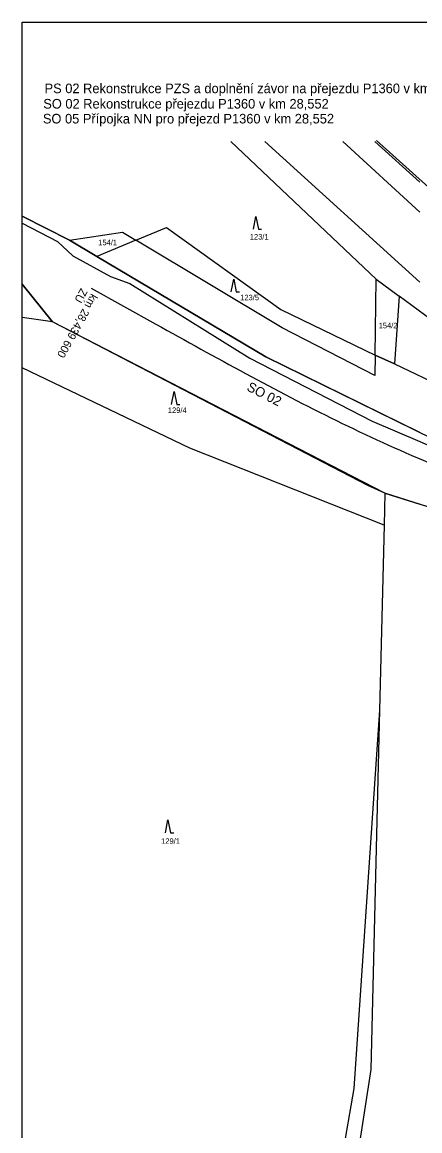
# Model space of a CAD drawing. Extents: x -792659 to -786947, y -1118170 to -1109641.
# Drawn here: x -789729.4 to -789667.2, y -1114376.9 to -1114203.8 of the extents above; entities that cross this region are included whole.
import ezdxf

# ---------------------------------------------------------------- set-up
doc = ezdxf.new("R2010")
doc.units = 0
doc.layers.add('1', color=7, linetype='Continuous')

# ---------------------------------------------------------------- blocks, each defined once
blk = doc.blocks.new('Z30801')
at = {"layer": '1'}
for p, q in [((-0.8, 0), (0, 4)), ((0, 4), (0.8, 0)), ((0.8, 0), (1.8, 0))]:
    blk.add_line(p, q, dxfattribs=at)

msp = doc.modelspace()

# ---------------------------------------------------------------- linework, layer by layer
at = {"layer": '1'}
for p, q in [((-789674.05, -1114243.92), (-789696.77, -1114222.42)), ((-789667.24, -1114244.36), (-789691.43, -1114222.42)), ((-789679.26, -1114222.42), (-789667.24, -1114233.46)), ((-789667.24, -1114228.73), (-789674.25, -1114222.42)), ((-789721.98, -1114237.82), (-789729.37, -1114234.09)), ((-789711.61, -1114237.83), (-789706.83, -1114235.81)), ((-789706.83, -1114235.81), (-789688.94, -1114248.62)), ((-789721.98, -1114237.82), (-789713.71, -1114236.57)), ((-789717.72, -1114240.35), (-789721.98, -1114237.82)), ((-789711.61, -1114237.83), (-789717.72, -1114240.35)), ((-789713.71, -1114236.57), (-789711.61, -1114237.83)), ((-789688.76, -1114251.49), (-789711.61, -1114237.83)), ((-789691.28, -1114256.01), (-789717.72, -1114240.35)), ((-789729.37, -1114244.66), (-789724.61, -1114250.58)), ((-789674.22, -1114255.79), (-789674.05, -1114243.92)), ((-789674.05, -1114243.92), (-789670.47, -1114246.55)), ((-789718.58, -1114245.32), (-789708.47, -1114250.93)), ((-789718.58, -1114245.32), (-789708.47, -1114250.93)), ((-789718.58, -1114245.32), (-789708.47, -1114250.93)), ((-789718.58, -1114245.32), (-789708.47, -1114250.93)), ((-789670.47, -1114246.55), (-789671.17, -1114257.11)), ((-789665.52, -1114250.19), (-789670.47, -1114246.55)), ((-789724.61, -1114250.58), (-789729.37, -1114249.9)), ((-789688.94, -1114248.62), (-789674.22, -1114255.79)), ((-789675.34, -1114276.11), (-789724.61, -1114250.58)), ((-789674.27, -1114258.96), (-789688.76, -1114251.49)), ((-789667.24, -1114267.85), (-789691.28, -1114256.01)), ((-789674.22, -1114255.79), (-789674.27, -1114258.96)), ((-789674.22, -1114255.79), (-789671.17, -1114257.11)), ((-789671.17, -1114257.11), (-789674.22, -1114255.79)), ((-789703.15, -1114270.28), (-789729.37, -1114257.73)), ((-789671.17, -1114257.11), (-789662.15, -1114261.44)), ((-789672.8, -1114282.32), (-789703.15, -1114270.28)), ((-789672.68, -1114277.31), (-789675.34, -1114276.11)), ((-789672.68, -1114277.31), (-789672.8, -1114282.32)), ((-789672.68, -1114277.31), (-789667.24, -1114279.04)), ((-789672.8, -1114282.32), (-789673.52, -1114311.19)), ((-789673.52, -1114311.19), (-789677.54, -1114370.31)), ((-789673.52, -1114311.19), (-789674.91, -1114367.33)), ((-789674.91, -1114367.33), (-789681.24, -1114408.94)), ((-789677.54, -1114370.31), (-789686.2, -1114419.31))]:
    msp.add_line(p, q, dxfattribs=at)
msp.add_lwpolyline([(-789729.37, -1114203.77), (-789353, -1114203.77), (-789353, -1114466.81), (-789729.37, -1114466.81)], close=True, dxfattribs=at)
for points in [[(-789674.01, -1114222.23), (-789653.09, -1114241.04), (-789626.09, -1114265.17), (-789585.65, -1114277.76), (-789547.21, -1114285.57), (-789509.71, -1114297.22), (-789475.12, -1114308.28), (-789456.08, -1114314.36), (-789451.57, -1114315.81)], [(-789534.18, -1114315.38), (-789561.38, -1114306.6), (-789562.23, -1114306.39), (-789592.9, -1114298.82), (-789600.46, -1114294.39), (-789619.3, -1114290.36), (-789624.34, -1114291.37), (-789641.23, -1114287.32), (-789672.68, -1114277.31), (-789724.61, -1114250.58), (-789729.37, -1114244.66), (-789729.37, -1114234.09), (-789721.98, -1114237.82), (-789717.72, -1114240.35), (-789691.28, -1114256.01), (-789665.23, -1114268.84), (-789640.19, -1114272.7), (-789627.07, -1114282.33), (-789607.19, -1114286.63), (-789603.91, -1114286.39), (-789562.23, -1114295.42), (-789557.19, -1114296.51), (-789534.19, -1114304.37)], [(-789729.37, -1114235.18), (-789723.86, -1114238), (-789721.43, -1114240.25), (-789715.58, -1114243.5), (-789712.53, -1114244.57), (-789693.8, -1114256.22), (-789674.69, -1114266.08), (-789667.24, -1114269.28), (-789659.83, -1114272.47), (-789642.29, -1114278.58), (-789637.66, -1114279.92), (-789636.67, -1114276.5), (-789634.93, -1114276.11), (-789616.44, -1114277), (-789610.6, -1114282.06), (-789604.23, -1114283.25)], [(-789729.37, -1114235.18), (-789723.86, -1114238), (-789721.43, -1114240.25), (-789715.58, -1114243.5), (-789712.53, -1114244.57), (-789693.8, -1114256.22), (-789674.69, -1114266.08), (-789667.24, -1114269.28), (-789659.83, -1114272.47), (-789642.29, -1114278.58), (-789637.66, -1114279.92), (-789636.67, -1114276.5), (-789634.93, -1114276.11), (-789616.44, -1114277), (-789610.6, -1114282.06), (-789604.23, -1114283.25)], [(-789708.47, -1114250.93), (-789707.6, -1114251.41), (-789706.72, -1114251.9), (-789705.85, -1114252.38), (-789704.97, -1114252.87), (-789704.1, -1114253.35), (-789703.22, -1114253.84), (-789702.35, -1114254.32), (-789701.47, -1114254.81), (-789700.6, -1114255.29), (-789699.72, -1114255.77), (-789698.85, -1114256.25), (-789697.97, -1114256.73), (-789697.09, -1114257.21), (-789696.21, -1114257.69), (-789695.33, -1114258.17), (-789694.45, -1114258.64), (-789693.57, -1114259.12), (-789692.69, -1114259.59), (-789691.81, -1114260.06), (-789690.93, -1114260.53), (-789690.04, -1114261), (-789689.16, -1114261.46), (-789688.27, -1114261.93), (-789687.38, -1114262.39), (-789686.5, -1114262.85), (-789685.61, -1114263.3), (-789684.72, -1114263.76), (-789683.83, -1114264.21), (-789682.93, -1114264.66), (-789682.04, -1114265.11), (-789681.14, -1114265.55), (-789680.25, -1114266), (-789679.35, -1114266.44), (-789678.45, -1114266.87), (-789677.55, -1114267.3), (-789676.64, -1114267.73), (-789675.74, -1114268.16), (-789674.83, -1114268.59), (-789673.93, -1114269), (-789673.02, -1114269.42)], [(-789708.47, -1114250.93), (-789707.6, -1114251.41), (-789706.72, -1114251.9), (-789705.85, -1114252.38), (-789704.97, -1114252.87), (-789704.1, -1114253.35), (-789703.22, -1114253.84), (-789702.35, -1114254.32), (-789701.47, -1114254.81), (-789700.6, -1114255.29), (-789699.72, -1114255.77), (-789698.85, -1114256.25), (-789697.97, -1114256.73), (-789697.09, -1114257.21), (-789696.21, -1114257.69), (-789695.33, -1114258.17), (-789694.45, -1114258.64), (-789693.57, -1114259.12), (-789692.69, -1114259.59), (-789691.81, -1114260.06), (-789690.93, -1114260.53), (-789690.04, -1114261), (-789689.16, -1114261.46), (-789688.27, -1114261.93), (-789687.38, -1114262.39), (-789686.5, -1114262.85), (-789685.61, -1114263.3), (-789684.72, -1114263.76), (-789683.83, -1114264.21), (-789682.93, -1114264.66), (-789682.04, -1114265.11), (-789681.14, -1114265.55), (-789680.25, -1114266), (-789679.35, -1114266.44), (-789678.45, -1114266.87), (-789677.55, -1114267.3), (-789676.64, -1114267.73), (-789675.74, -1114268.16), (-789674.83, -1114268.59), (-789673.93, -1114269), (-789673.02, -1114269.42)], [(-789708.47, -1114250.93), (-789707.6, -1114251.41), (-789706.72, -1114251.9), (-789705.85, -1114252.38), (-789704.97, -1114252.87), (-789704.1, -1114253.35), (-789703.22, -1114253.84), (-789702.35, -1114254.32), (-789701.47, -1114254.81), (-789700.6, -1114255.29), (-789699.72, -1114255.77), (-789698.85, -1114256.25), (-789697.97, -1114256.73), (-789697.09, -1114257.21), (-789696.21, -1114257.69), (-789695.33, -1114258.17), (-789694.45, -1114258.64), (-789693.57, -1114259.12), (-789692.69, -1114259.59), (-789691.81, -1114260.06), (-789690.93, -1114260.53), (-789690.04, -1114261), (-789689.16, -1114261.46), (-789688.27, -1114261.93), (-789687.38, -1114262.39), (-789686.5, -1114262.85), (-789685.61, -1114263.3), (-789684.72, -1114263.76), (-789683.83, -1114264.21), (-789682.93, -1114264.66), (-789682.04, -1114265.11), (-789681.14, -1114265.55), (-789680.25, -1114266), (-789679.35, -1114266.44), (-789678.45, -1114266.87), (-789677.55, -1114267.3), (-789676.64, -1114267.73), (-789675.74, -1114268.16), (-789674.83, -1114268.59), (-789673.93, -1114269), (-789673.02, -1114269.42)], [(-789708.47, -1114250.93), (-789707.6, -1114251.41), (-789706.72, -1114251.9), (-789705.85, -1114252.38), (-789704.97, -1114252.87), (-789704.1, -1114253.35), (-789703.22, -1114253.84), (-789702.35, -1114254.32), (-789701.47, -1114254.81), (-789700.6, -1114255.29), (-789699.72, -1114255.77), (-789698.85, -1114256.25), (-789697.97, -1114256.73), (-789697.09, -1114257.21), (-789696.21, -1114257.69), (-789695.33, -1114258.17), (-789694.45, -1114258.64), (-789693.57, -1114259.12), (-789692.69, -1114259.59), (-789691.81, -1114260.06), (-789690.93, -1114260.53), (-789690.04, -1114261), (-789689.16, -1114261.46), (-789688.27, -1114261.93), (-789687.38, -1114262.39), (-789686.5, -1114262.85), (-789685.61, -1114263.3), (-789684.72, -1114263.76), (-789683.83, -1114264.21), (-789682.93, -1114264.66), (-789682.04, -1114265.11), (-789681.14, -1114265.55), (-789680.25, -1114266), (-789679.35, -1114266.44), (-789678.45, -1114266.87), (-789677.55, -1114267.3), (-789676.64, -1114267.73), (-789675.74, -1114268.16), (-789674.83, -1114268.59), (-789673.93, -1114269), (-789673.02, -1114269.42)]]:
    msp.add_lwpolyline(points, dxfattribs=at)
msp.add_arc((-789569.36, -1114041.92), 250, 245.505, 252.7337, dxfattribs=at)
msp.add_arc((-789569.36, -1114041.92), 250, 245.505, 252.7337, dxfattribs=at)
msp.add_arc((-789569.36, -1114041.92), 250, 245.505, 252.7337, dxfattribs=at)
msp.add_arc((-789569.36, -1114041.92), 250, 245.505, 252.7337, dxfattribs=at)

# ---------------------------------------------------------------- block references
at = {"layer": '1', "xscale": 0.5, "yscale": 0.5}
for p in [(-789692.85, -1114236.11), (-789696.31, -1114245.89), (-789705.62, -1114263.46), (-789706.59, -1114330.36)]:
    msp.add_blockref('Z30801', p, dxfattribs=at)

# ---------------------------------------------------------------- texts
at = {"layer": '1'}
for s, height, p in [('PS 02 Rekonstrukce PZS a doplnění závor na přejezdu P1360 v km 28,552', 1.5, (-789725.87, -1114214.86)), ('SO 02 Rekonstrukce přejezdu P1360 v km 28,552', 1.5, (-789726.07, -1114217.26)), ('SO 05 Přípojka NN pro přejezd P1360 v km 28,552', 1.5, (-789726.13, -1114219.59)), ('154/1', 0.85, (-789717.48, -1114238.6)), ('123/1', 0.85, (-789693.8, -1114237.71)), ('123/5', 0.85, (-789695.3, -1114247.19)), ('154/2', 0.85, (-789673.67, -1114251.57)), ('129/4', 0.85, (-789706.6, -1114264.79)), ('129/1', 0.85, (-789707.66, -1114332.08))]:
    msp.add_text(s, height=height, dxfattribs=at).set_placement(p)
for s, height, rotation, p in [('km 28,439 600', 1.25, 240.9213, (-789718.59, -1114246.07)), ('ZÚ', 1.25, 241.1644, (-789720.18, -1114245.21)), ('SO 02', 1.5, 332.8766, (-789694.4, -1114261.21))]:
    msp.add_text(s, height=height, rotation=rotation, dxfattribs=at).set_placement(p)

doc.saveas('drawing.dxf')
